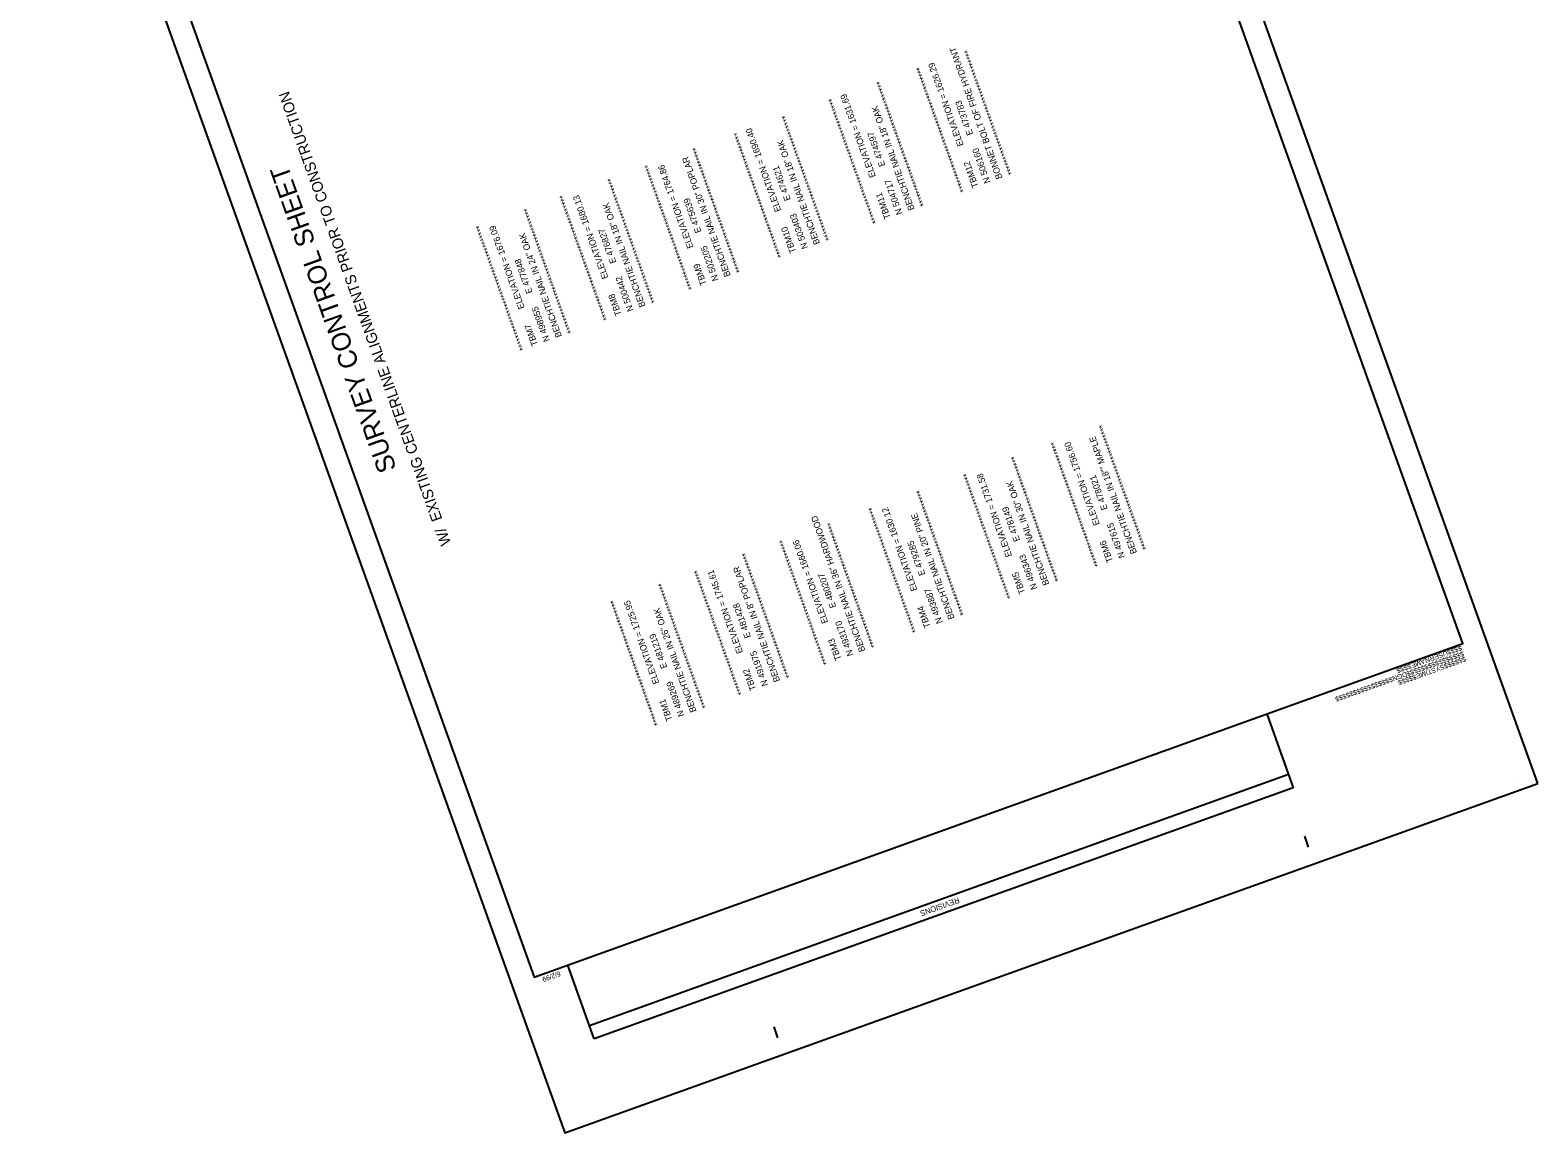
# Model space of a CAD drawing. Extents: x 471172 to 474725, y 509605 to 513938.
# Drawn here: x 471172 to 474725, y 509605 to 512203 of the extents above; entities that cross this region are included whole.
import ezdxf

# ---------------------------------------------------------------- set-up
doc = ezdxf.new("R2010")
doc.units = 0
for name, color, linetype in [('CTL Sheet Border CELL', 7, 'Continuous'), ('CTL Sheet Text', 7, 'Continuous'), ('Sheet Block Revision CELL', 7, 'Continuous'), ('Sheet Plot Border Outside CELL', 7, 'Continuous')]:
    doc.layers.add(name, color=color, linetype=linetype)

msp = doc.modelspace()

# ---------------------------------------------------------------- linework, layer by layer
at = {"layer": 'CTL Sheet Border CELL'}
for p, q in [((474548.4, 510757.7), (474548.4, 510757.7)), ((474548.4, 510757.7), (474548.4, 510757.7)), ((474548.4, 510757.7), (474548.4, 510757.7)), ((474548.4, 510757.7), (474548.4, 510757.7)), ((474548.4, 510757.7), (474548.4, 510757.7)), ((474548.4, 510757.7), (474548.4, 510757.7)), ((474548.4, 510757.7), (474548.4, 510757.7)), ((474548.4, 510757.7), (474548.4, 510757.7)), ((474548.4, 510757.7), (474548.4, 510757.7)), ((474548.4, 510757.7), (474548.4, 510757.7)), ((474548.4, 510757.7), (474548.4, 510757.7)), ((474669, 510438.6), (474669, 510438.6)), ((474725.5, 510428.3), (474725.5, 510428.3)), ((474185.3, 510277.9), (474176, 510303.9)), ((472934.7, 509828.9), (472925.4, 509854.9))]:
    msp.add_line(p, q, dxfattribs=at)
msp.add_lwpolyline([(471237.2, 513098.5), (472359.8, 509971.9), (474548.4, 510757.7), (473425.8, 513884.3)], close=True, dxfattribs=at)
msp.add_lwpolyline([(474520.3, 510835.9), (474520.3, 510835.9)], dxfattribs=at)
msp.add_lwpolyline([(474520.3, 510835.9), (474520.3, 510835.9)], dxfattribs=at)
at = {"layer": 'Sheet Block Revision CELL'}
for p, q in [((474086.7, 510591.9), (474149.2, 510417.9)), ((474138, 510449.1), (472490.4, 509857.5)), ((474149.2, 510417.9), (472501.7, 509826.3)), ((472501.7, 509826.3), (472439.1, 510000.3))]:
    msp.add_line(p, q, dxfattribs=at)
at = {"layer": 'Sheet Plot Border Outside CELL'}
msp.add_lwpolyline([(474725.5, 510428.3), (473465.2, 513938.4), (471172.4, 513115.2), (472432.7, 509605.1)], close=True, dxfattribs=at)

# ---------------------------------------------------------------- texts
at = {"layer": 'CTL Sheet Border CELL'}
for s, height, rotation, p in [('W/  EXISTING CENTERLINE ALIGNMENTS PRIOR TO CONSTRUCTION', 25.469, 109.7508, (472164.5, 510994)), ('SURVEY CONTROL SHEET ', 44.294, 109.7508, (472036.4, 511169.8)), ('$$$$$$$$$$$$$$$$DGN$$$$$$$$$$$$$$$$', 11.627, 199.7508, (474549.2, 510740)), ('$$$$USERNAME$$$$', 11.627, 199.7508, (474544.2, 510753.7)), ('$$$$$$SYSTIME$$$$$', 11.627, 199.7508, (474553.7, 510727.4)), ('6/2/99', 11.63, 199.7508, (472420, 509986.1))]:
    msp.add_text(s, height=height, rotation=rotation, dxfattribs=at).set_placement(p)
at = {"layer": 'CTL Sheet Text'}
for s, p in [('BONNET BOLT OF FIRE HYDRANT', (473463.9, 511855)), ('****************************************', (473492.2, 511865.1)), ('****************************************', (473379.2, 511824.6)), ('TBM12       ELEVATION = 1626.29', (473407.5, 511834.7)), ('****************************************', (473285.2, 511791.3)), ('****************************************', (473172.2, 511750.8)), ('TBM11       ELEVATION = 1631.69', (473200.5, 511760.9)), ('BENCHTIE NAIL IN 18" OAK', (473256.9, 511781.2)), ('N 506160      E 473783', (473435.7, 511844.8)), ('TBM10       ELEVATION = 1690.40', (472977.4, 511680.4)), ('****************************************', (473062.1, 511710.8)), ('****************************************', (472949.2, 511670.3)), ('BENCHTIE NAIL IN 18" OAK', (473033.9, 511700.7)), ('N 504717      E 474597', (473228.7, 511771)), ('BENCHTIE NAIL IN 30" POPLAR', (472823.5, 511624.9)), ('****************************************', (472851.7, 511635.1)), ('****************************************', (472738.8, 511594.5)), ('TBM9       ELEVATION = 1764.86', (472767, 511604.6)), ('N 503403      E 474621', (473005.7, 511690.5)), ('****************************************', (472651.2, 511563.2)), ('****************************************', (472538.2, 511522.7)), ('TBM8       ELEVATION = 1680.13', (472566.5, 511532.8)), ('BENCHTIE NAIL IN 18" OAK', (472622.9, 511553.1)), ('N 502205      E 475639', (472795.3, 511614.8)), ('****************************************', (472453.9, 511492.1)), ('****************************************', (472341, 511451.6)), ('TBM7       ELEVATION = 1676.09', (472369.2, 511461.7)), ('BENCHTIE NAIL IN 24" OAK', (472425.7, 511482)), ('N 500442      E 476827', (472594.7, 511542.9)), ('N 498955      E 477848', (472397.4, 511471.8)), ('****************************************', (473809.2, 510982.2)), ('****************************************', (473696.2, 510941.6)), ('TBM6       ELEVATION = 1756.60', (473724.5, 510951.8)), ('BENCHTIE NAIL IN 18"" MAPLE', (473780.9, 510972.1)), ('****************************************', (473602.5, 510908)), ('****************************************', (473489.6, 510867.4)), ('TBM5       ELEVATION = 1731.58', (473517.8, 510877.6)), ('N 497615      E 478021', (473752.7, 510961.9)), ('****************************************', (473379.3, 510827.9)), ('BENCHTIE NAIL IN 30" OAK', (473574.3, 510897.8)), ('BENCHTIE NAIL IN 36" HARDWOOD', (473140.9, 510741.3)), ('****************************************', (473266.4, 510787.3)), ('TBM4       ELEVATION = 1630.12', (473294.6, 510797.4)), ('BENCHTIE NAIL IN 20" PINE', (473351.1, 510817.7)), ('N 496343      E 478149', (473546.1, 510887.7)), ('****************************************', (473169.1, 510751.4)), ('****************************************', (473056.2, 510710.9)), ('TBM3       ELEVATION = 1660.06', (473084.4, 510721)), ('N 493887      E 479285', (473322.9, 510807.6)), ('BENCHTIE NAIL IN 8" POPLAR', (472940, 510670.3)), ('****************************************', (472968.3, 510680.4)), ('****************************************', (472855.3, 510639.9)), ('TBM2       ELEVATION = 1745.61', (472883.6, 510650)), ('N 493170      E 480207', (473112.7, 510731.2)), ('****************************************', (472771.1, 510608.8)), ('****************************************', (472658.1, 510568.2)), ('TBM1       ELEVATION = 1725.95', (472686.4, 510578.3)), ('BENCHTIE NAIL IN 26" OAK', (472742.8, 510598.6)), ('N 491975      E 481428', (472911.8, 510660.2)), ('N 489269      E 481219', (472714.6, 510588.5))]:
    msp.add_text(s, height=15, rotation=109.7508, dxfattribs=at).set_placement(p)
at = {"layer": 'Sheet Block Revision CELL'}
msp.add_text('REVISIONS', height=13.28, rotation=199.7508, dxfattribs=at).set_placement((473359.5, 510160.3))

doc.saveas('drawing.dxf')
